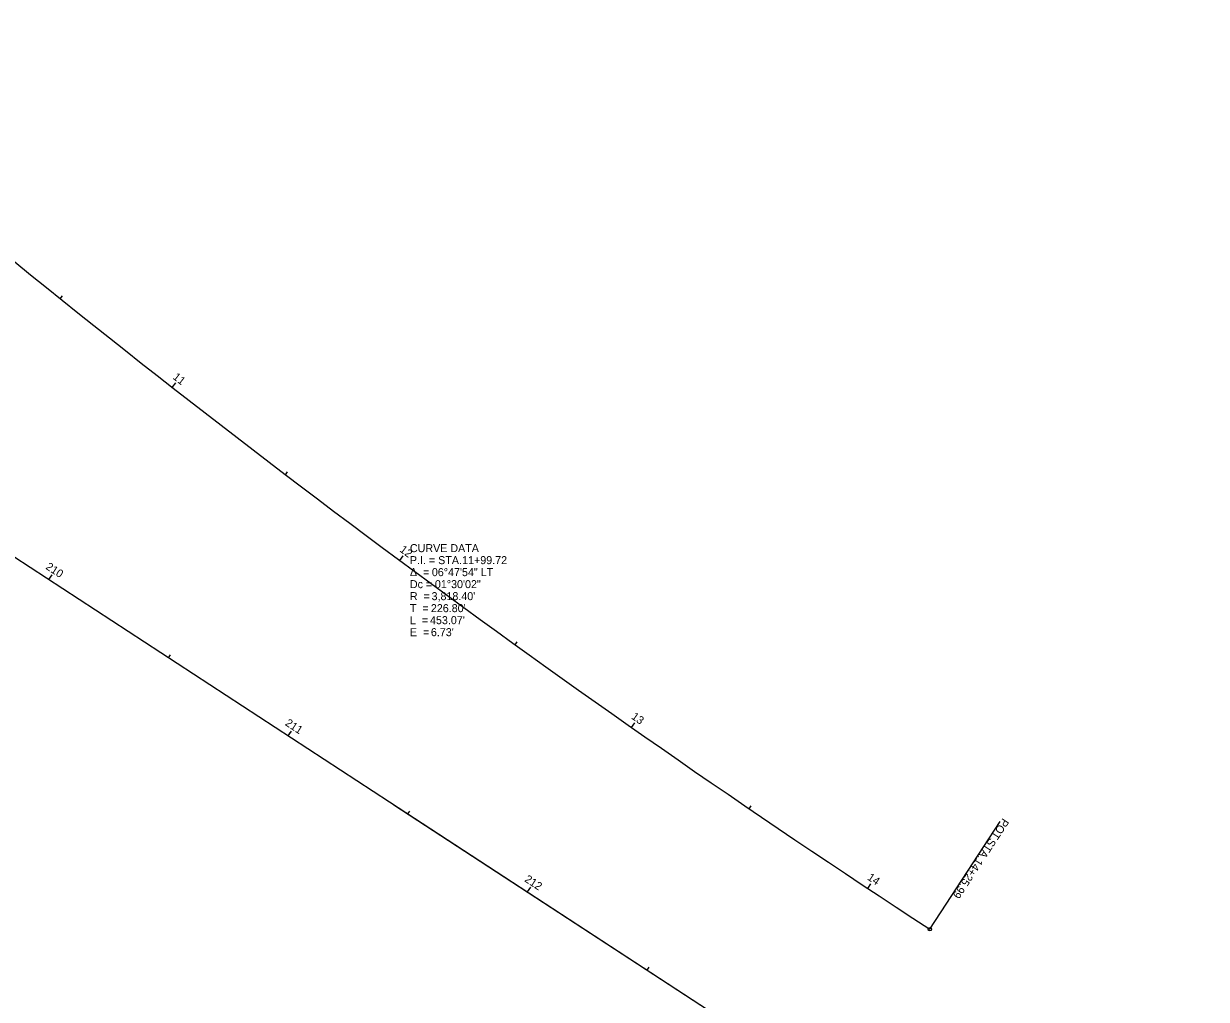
# Model space of a CAD drawing. Extents: x 1323137 to 1326838, y 458936 to 461644.
# Drawn here: x 1326010.6 to 1326424.4, y 459305.6 to 459647 of the extents above; entities that cross this region are included whole.
import ezdxf

# ---------------------------------------------------------------- set-up
doc = ezdxf.new("R2010")
doc.units = 0
for name, color, linetype in [('CM_Corridor_Range_Final', 7, 'Continuous'), ('Default', 7, 'Continuous'), ('MD_P_ACB_B', 7, 'Continuous'), ('MD_P_AGB_T', 7, 'Continuous'), ('SG_P_Conduit', 7, 'Continuous'), ('SG_P_Mast_Arm', 7, 'Continuous'), ('SN_P_Signs', 7, 'Continuous'), ('SN_X_Public', 7, 'Continuous')]:
    doc.layers.add(name, color=color, linetype=linetype)

msp = doc.modelspace()

# ---------------------------------------------------------------- linework, layer by layer
at = {"layer": 'CM_Corridor_Range_Final'}
for p, q in [((1326019.42, 459452.5), (1326020.52, 459454.17)), ((1326061.3, 459425.17), (1326061.95, 459426.18)), ((1326103.17, 459397.85), (1326104.26, 459399.52)), ((1326145.04, 459370.52), (1326145.7, 459371.53)), ((1326186.92, 459343.2), (1326188.01, 459344.87)), ((1326228.79, 459315.87), (1326229.44, 459316.88))]:
    msp.add_line(p, q, dxfattribs=at)
at = {"layer": 'Default'}
msp.add_line((1325721.36, 459647), (1326810.06, 458936.55), dxfattribs=at)
msp.add_arc((1328414.31, 462527.99), 3818.4, 230.07643, 236.87482, dxfattribs=at)
at = {"layer": 'MD_P_ACB_B'}
msp.add_line((1326327.67, 459330.16), (1326352.26, 459367.84), dxfattribs=at)
msp.add_circle((1326327.67, 459330.16), 0.6, dxfattribs=at)
at = {"layer": 'SG_P_Conduit'}
msp.add_arc((1328414.31, 462527.99), 3818.4, 230.07643, 236.87482, dxfattribs=at)
at = {"layer": 'SG_P_Mast_Arm'}
for p, q in [((1326023.4, 459550.78), (1326024.15, 459551.72)), ((1326062.59, 459519.73), (1326063.82, 459521.31)), ((1326102.18, 459489.2), (1326102.91, 459490.15)), ((1326142.17, 459459.18), (1326143.36, 459460.79)), ((1326182.55, 459429.69), (1326183.25, 459430.67)), ((1326223.31, 459400.74), (1326224.45, 459402.37)), ((1326264.44, 459372.31), (1326265.12, 459373.31)), ((1326305.95, 459344.43), (1326307.05, 459346.1))]:
    msp.add_line(p, q, dxfattribs=at)
at = {"layer": 'SN_P_Signs'}
for p in [(1325721.36, 459647), (1326140.09, 459373.75)]:
    msp.add_line(p, (1326810.06, 458936.55), dxfattribs=at)
msp.add_arc((1328414.31, 462527.99), 3818.4, 230.07643, 236.87482, dxfattribs=at)
at = {"layer": 'SN_X_Public'}
for p, q in [((1326019.42, 459452.5), (1326020.52, 459454.17)), ((1326103.17, 459397.85), (1326103.83, 459398.85)), ((1326186.92, 459343.2), (1326187.57, 459344.2))]:
    msp.add_line(p, q, dxfattribs=at)

# ---------------------------------------------------------------- texts
at = {"layer": 'CM_Corridor_Range_Final'}
for s, p in [('210', (1326018.05, 459456.37)), ('211', (1326101.84, 459401.7)), ('212', (1326185.59, 459347.04))]:
    msp.add_text(s, height=2.8, rotation=326.873, dxfattribs=at).set_placement(p)
at = {"layer": 'MD_P_ACB_B'}
for s, p in [('POT', (1326353.2, 459369.21)), (' STA. ', (1326349.26, 459363.17)), ('14+25.99', (1326344.1, 459355.26))]:
    msp.add_text(s, height=2.8, rotation=236.8748, dxfattribs=at).set_placement(p)
at = {"layer": 'MD_P_AGB_T'}
for s, p in [('CURVE DATA', (1326145.73, 459462.1)), ('P.I. = STA. ', (1326145.73, 459457.9)), ('11+99.72', (1326164, 459457.9)), ('Δ  = ', (1326145.73, 459453.7)), ('06°47\'54" LT', (1326153.41, 459453.7)), ('01°30\'02"', (1326154.47, 459449.5)), ('Dc = ', (1326145.73, 459449.5)), ('R  = ', (1326145.73, 459445.3)), ("3,818.40'", (1326153.31, 459445.3)), ('T  = ', (1326145.73, 459441.1)), ("226.80'", (1326153.07, 459441.1)), ('L  = ', (1326145.73, 459436.9)), ("453.07'", (1326152.77, 459436.9)), ('E  = ', (1326145.73, 459432.7)), ("6.73'", (1326153.07, 459432.7))]:
    msp.add_text(s, height=2.8, dxfattribs=at).set_placement(p)
at = {"layer": 'SG_P_Mast_Arm'}
for s, rotation, p in [('11', 321.9832, (1326062.52, 459522.95)), ('12', 323.4838, (1326141.92, 459462.48)), ('13', 324.9843, (1326222.98, 459404.02)), ('14', 326.4848, (1326305.53, 459347.71))]:
    msp.add_text(s, height=2.8, rotation=rotation, dxfattribs=at).set_placement(p)
at = {"layer": 'SN_X_Public'}
msp.add_text('210', height=2.8, rotation=326.873, dxfattribs=at).set_placement((1326018.05, 459456.37))

doc.saveas('drawing.dxf')
